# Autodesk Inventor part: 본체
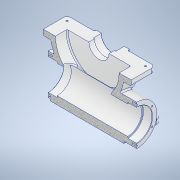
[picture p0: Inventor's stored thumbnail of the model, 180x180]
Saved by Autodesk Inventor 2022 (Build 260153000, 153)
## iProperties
Created: 2023-07
Part Number: 본체
Material: 알루미늄 6061
Document SubType Name: Modeling
Designer: PC-01
Density: 2.7 g/cm^3
Appearance: 알루미늄 - 평지
Author: PC-01
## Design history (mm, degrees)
sketch "스케치1"
  geometry: C1 r 55 at (0, 0); 1 further point
  constraints: 1 centre point, 1 coincident
  dimensions: "d0" = 110 diameter of C1
extrude "돌출1" new body sketch "스케치1" stored distance "d1" = 242; taper "d2" = 0 deg
sketch "스케치2"
  geometry: C1 r 42.5 at (0, 0); 1 further point
  constraints: 1 centre point, 1 coincident
  dimensions: "d3" = 85 diameter of C1
extrude "돌출2" cut sketch "스케치2" distance "d4" = 25; taper "d5" = 0 deg
sketch "스케치3" dims "d6" = 97
  geometry: L1 (0, 0)-(0, 48.5); 1 further point
  constraints: 2 end point, 1 coincident, 1 vertical, 1 vertical alignment, 2 other
hole "구멍1" sketch "스케치3" at (0, 48.5) diameter "d7" = 4.134; stored, may be unused: countersink angle "d11" = 90 deg, drill point angle "d13" = 118 deg; dims "d8" = 10, "d9" = 4, "d10" = 2, "d12" = 12
sketch "스케치4"
  geometry: C1 r 38.5 at (0, 0); 1 further point
  constraints: 1 centre point, 1 coincident
  dimensions: "d17" = 77 diameter of C1
extrude "돌출3" cut sketch "스케치4" extent not by distance; stored distance "d18" = 0; taper "d19" = 0 deg
node "작업 평면1"
sketch "스케치5"
  geometry: L1 (114, -100)-(-86, -100); L2 (-86, -100)-(-86, 100); L3 (-86, 100)-(114, 100); L4 (114, 100)-(114, -100); L5 (121, -55)-(121, 55) reference; 2 further points
  constraints: 8 end point, 2 parallel, 1 horizontal, 1 horizontal alignment, 1 midpoint, 1 perpendicular
  dimensions: "d21" = 200 distance of L1.end L2.end; "d22" = 200 distance of L1.start L1.end; "d23" = 7 distance between parallel lines of L4 L5
extrude "돌출4" join sketch "스케치5" distance "d24" = 15; taper "d25" = 0 deg
sketch "스케치7" dims "d35" = 200
  geometry: L1 (-14, 100)-(-14, -60); L2 (86, -60)-(-114, -60) reference; L3 (-14, 100)-(-134, 100); L4 (-134, 100)-(-134, 85); L5 (-134, 85)-(-112.869, 85); L6 (-14, 100)-(106, 100); L7 (106, 100)-(106, 85); L8 (106, 85)-(84.869, 85); 2 further points
  constraints: 14 end point, 3 symmetric about line, 2 perpendicular, 1 coincident, 1 horizontal, 1 midpoint, 1 vertical, 3 other
  dimensions: "d34" = 160 distance of L1.start L1.end; "d36" = 120 distance of L3.start L3.end; "d37" = 15 distance of L3.end L4.end
extrude "돌출6" join sketch "스케치7" stored distance "d38" = 130; taper "d39" = 0 deg
sketch "스케치8"
  geometry: L1 (-134, 100)-(106, 100) reference; L2 (31, 100)-(-59, 100); A1 r 45 centre (-14, 100) between (-59, 100) and (31, 100); 1 further point
  constraints: 2 end point, 2 point on circle, 2 point on line, 1 centre point, 1 horizontal, 1 midpoint
  dimensions: "d40" = 90 diameter of A1
extrude "돌출7" join sketch "스케치8" distance "d41" = 5; taper "d42" = 0 deg
sketch "스케치9"
  geometry: L1 (31, 100)-(-59, 100) reference; C1 r 31 at (-14, 100); A1 r 45 centre (-14, 100) between (-59, 100) and (31, 100) reference; 1 further point
  constraints: 1 centre point, 1 coincident
  dimensions: "d43" = 62 diameter of C1
extrude "돌출8" cut sketch "스케치9" distance "d44" = 23; taper "d45" = 0 deg
sketch "스케치10"
  geometry: L1 (-45, 100)-(17, 100) reference; C1 r 27.5 at (-14, 100); A1 r 31 centre (-14, 100) between (-45, 100) and (17, 100) reference; 1 further point
  constraints: 1 centre point, 1 coincident
  dimensions: "d46" = 55 diameter of C1
extrude "돌출9" cut sketch "스케치10" extent not by distance; stored distance "d47" = 23; taper "d48" = 0 deg
sketch "스케치11"
  geometry: L1 (31, 100)-(17, 100) reference; L2 (-45, 100)-(-59, 100) reference; C1 r 87 at (-14, 100); A1 r 31 centre (-14, 100) between (-45, 100) and (17, 100) reference; A2 r 45 centre (-14, 100) between (-59, 100) and (31, 100) reference; 1 further point
  constraints: 1 centre point, 1 coincident
  dimensions: "d49" = 174 diameter of C1
  node "투영된 루프3"
extrude "돌출10" cut sketch "스케치11" stored distance "d50" = 64; taper "d51" = 0 deg
extrude "돌출11" cut sketch "스케치4" extent not by distance; stored distance "d52" = 0; taper "d53" = 0 deg
fillet "모깎기1" dims "d54" = 10
fillet "모깎기2" dims "d55" = 10
sketch "스케치12"
  geometry: L1 (-114, 90)-(-114, 31.623) reference; L2 (86, 31.623)-(-114, 31.623) reference; L3 (86, 31.623)-(86, 90) reference; L4 (76, 100)-(-104, 100) reference; L5 (86, -90)-(86, -31.623) reference; L6 (-114, -31.623)-(86, -31.623) reference; L7 (-114, -31.623)-(-114, -90) reference; L8 (-104, -100)-(76, -100) reference; L9 (76, 100)-(-104, 100) reference; L10 (-104, -100)-(76, -100) reference; L11 (-14, -100)-(-14, -119.667); C1 r 14 at (-94, 80); C2 r 14 at (66, 80); C3 r 14 at (-94, -80); C4 r 14 at (66, -80); A1 r 10 centre (-104, 90) between (-104, 100) and (-114, 90) reference; A2 r 10 centre (76, 90) between (86, 90) and (76, 100) reference; A3 r 10 centre (76, -90) between (76, -100) and (86, -90) reference; A4 r 10 centre (-104, -90) between (-114, -90) and (-104, -100) reference; 1 further point
  constraints: 4 centre point, 2 end point, 2 horizontal alignment, 2 vertical alignment, 1 midpoint, 1 vertical
  dimensions: "d56" = 28 diameter of C1; "d57" = 28 diameter of C2; "d58" = 28 diameter of C3; "d59" = 28 diameter of C4; "d60" = 160 distance of C3.centre C1.centre; "d61" = 160 distance of C2.centre C1.centre; "d62" = 80 vertical distance of point (0, 0) C1.centre; "d63" = 80 horizontal distance of L11.start C1.centre
extrude "돌출12" cut sketch "스케치12" distance "d64" = 2; taper "d65" = 0 deg
sketch "스케치13"
  geometry: C1 r 14 at (0, 0) reference; 2 further points
  constraints: 1 coincident
hole "구멍2" sketch "스케치13" at (0, 0) diameter "d66" = 11; stored, may be unused: countersink angle "d70" = 90 deg, drill point angle "d72" = 118 deg; dims "d67" = 10, "d68" = 4, "d69" = 2, "d71" = 12
sketch "스케치14"
  geometry: C1 r 14 at (0, 0) reference; 2 further points
  constraints: 1 coincident
hole "구멍3" sketch "스케치14" at (0, 0) diameter "d73" = 11; stored, may be unused: countersink angle "d77" = 90 deg, drill point angle "d79" = 118 deg; dims "d74" = 6, "d75" = 4, "d76" = 2, "d78" = 12
sketch "스케치15"
  geometry: C1 r 14 at (0, 0) reference; 2 further points
  constraints: 1 coincident
hole "구멍4" sketch "스케치15" at (0, 0) diameter "d80" = 11; stored, may be unused: countersink angle "d84" = 90 deg, drill point angle "d86" = 118 deg; dims "d81" = 6, "d82" = 4, "d83" = 2, "d85" = 12
sketch "스케치16"
  geometry: C1 r 14 at (0, 0) reference; 2 further points
  constraints: 1 coincident
hole "구멍5" sketch "스케치16" at (0, 0) diameter "d87" = 11; stored, may be unused: countersink angle "d91" = 90 deg, drill point angle "d93" = 118 deg; dims "d88" = 6, "d89" = 4, "d90" = 2, "d92" = 12
sketch "스케치17"
  geometry: L1 (-62, 114.069)-(-50, 114.069) reference; L2 (-75, 125)-(-75, 15) reference; L3 (0, 5)-(-65, 5) reference; L4 (0, 5)-(0, 0) reference; L5 (14, 0)-(0, 0) reference; L6 (14, 0)-(14, 23) reference; L7 (14, 23)-(17.5, 23) reference; L8 (17.5, 23)-(17.5, 38) reference; L9 (17.5, 38)-(-42, 38) reference; L10 (-42, 38)-(-42, 102) reference; L11 (-42, 102)-(17.5, 102) reference; L12 (17.5, 102)-(17.5, 117) reference; L13 (17.5, 117)-(14, 117) reference; L14 (14, 117)-(14, 140) reference; L15 (14, 140)-(0, 140) reference; L16 (0, 135)-(0, 140) reference; L17 (-65, 135)-(0, 135) reference; L18 (135, 170)-(-45, 170) reference; L19 (45, 170)-(45, 190.033); A1 r 10 centre (-65, 125) between (-65, 135) and (-75, 125) reference; A2 r 10 centre (-65, 15) between (-75, 15) and (-65, 5) reference; 5 further points
  constraints: 2 end point, 2 symmetric about line, 1 midpoint, 1 vertical, 1 vertical alignment
  dimensions: "d94" = 104 distance of point (-62, 18) point (-62, 122); "d95" = 52 vertical distance of point (59, 70) point (-62, 122); "d96" = 107 horizontal distance of L19.end point (-62, 122)
hole "구멍6" sketch "스케치17" at (-62, 122), (-62, 18), (152, 18), (152, 122) diameter "d97" = 4.917; stored, may be unused: countersink angle "d101" = 90 deg, drill point angle "d103" = 118 deg; dims "d98" = 10, "d99" = 4, "d100" = 2, "d102" = 12
sketch "스케치18"
  geometry: L1 (-45, 100)-(-59, 100) reference; L2 (31, 100)-(17, 100) reference; L3 (-14, 100)-(-14, 69); L4 (-14, 100)-(12.163, 73.837); L5 (-14, 100)-(-40.163, 73.837); A1 r 31 centre (-14, 100) between (-45, 100) and (17, 100) reference; A2 r 45 centre (-14, 100) between (-59, 100) and (31, 100) reference; A3 r 37 centre (-14, 100) between (12.163, 73.837) and (-40.163, 73.837); 1 further point
  constraints: 6 end point, 3 point on circle, 1 centre point, 1 coincident
  dimensions: "d104" = 74 diameter of A3; "d105" = 45 deg angle of L3 L4; "d106" = 45 deg angle of L3 L5
hole "구멍7" sketch "스케치18" at (-40.163, 73.837), (12.163, 73.837) diameter "d107" = 4.134; stored, may be unused: countersink angle "d111" = 90 deg, drill point angle "d113" = 118 deg; dims "d108" = 10, "d109" = 4, "d110" = 2, "d112" = 12
fillet "모깎기3" dims "d114" = 15
fillet "모깎기4" dims "d115" = 3
fillet "모깎기5" dims "d116" = 3
fillet "모깎기6" dims "d117" = 3
fillet "모깎기8" dims "d119" = 1
chamfer "모따기1" distance "d120" = 1; stored, may be unused: second distance "d121" = 2, angle "d122" = 45 deg
sketch "스케치19"
  geometry: L1 (-46, 100)-(-59, 100) reference; L2 (31, 100)-(18, 100) reference; L3 (-14, 100)-(-14, 85); L4 (96, 85)-(84.869, 85) reference; L5 (-14, 85)-(84.869, 85); L6 (-14, 85)-(-112.869, 85); C1 r 2.067 at (12.163, 73.837) reference; C2 r 2.067 at (-40.163, 73.837) reference; A1 r 32 centre (-14, 100) between (-46, 100) and (18, 100) reference; A2 r 45 centre (-14, 100) between (-59, 100) and (31, 100) reference; A3 r 100 centre (-14, 100) between (-114, 100) and (86, 100); 3 further points
  constraints: 6 end point, 3 point on circle, 2 point on line, 1 centre point, 1 coincident, 1 horizontal, 1 vertical
  dimensions: "d126" = 200 diameter of A3; "d127" = 15 distance of L3.start L3.end
extrude "돌출13" cut sketch "스케치19" distance "d128" = 20; taper "d129" = 0 deg
sketch "스케치20"
  geometry: L1 (0, 0)-(0, -55); L2 (0, 0)-(0, 55); L3 (0, 55)-(0, 45) reference; C1 r 55 at (0, 0); C2 r 38.5 at (0, 0) reference; C3 r 42.5 at (0, 0) reference; A1 r 55 centre (0, 0) between (0, -55) and (0, 55) reference; 5 further points
  constraints: 4 end point, 2 point on circle, 1 centre point, 1 coincident, 1 point on line, 1 vertical
  dimensions: "d130" = 110 diameter of C1
extrude "돌출14" join sketch "스케치20" stored distance "d131" = 210; taper "d132" = 0 deg
extrude "돌출15" cut sketch "스케치11" stored distance "d133" = 64; taper "d134" = 0 deg
fillet "모깎기12" dims "d135" = 3
fillet "모깎기13" dims "d136" = 3
fillet "모깎기14" dims "d137" = 3
fillet "모깎기15" dims "d138" = 3
fillet "모깎기16" dims "d139" = 3
fillet "모깎기17" dims "d140" = 3
fillet "모깎기18" dims "d141" = 3
sketch "스케치21"
  geometry: L1 (-104, -100)-(76, -100) reference; L2 (13.5, -47)-(-41.5, -47) reference; 3 further points
  constraints: 1 midpoint, 1 vertical alignment, 1 other
  dimensions: "d142" = 15 distance from line of L1 point (-14, -85)
feature "엠보싱1" sketch "스케치21" dims "d14" = 60, "d143" = 0.5, "d144" = 0
fillet "모깎기19" dims "d145" = 1.1
node "솔리드1"
pattern_circular "원형 패턴1" dims angle "d15" = 360 deg
mirror "미러1"
mirror "미러2"
mirror "미러3"
mirror "미러4"
mirror "미러5"
node "투영된 루프1"
node "투영된 루프2"
node "투영된 루프4"
node "투영된 루프5"
node "투영된 루프6"
node "투영된 루프7"
node "투영된 루프8"
node "투영된 루프9"
feature "A9D066F2-1C7D-4E18-AEED-F7BC21143FA4" dims "d66" = 11, "d67" = 10, "d68" = 4, "d69" = 2, "d70" = 90 deg, "d71" = 12, "d72" = 118 deg
